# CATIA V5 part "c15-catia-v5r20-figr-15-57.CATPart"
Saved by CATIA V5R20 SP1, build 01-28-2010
Part number: Part1
Bounding box of the stored display mesh (mm): x -92.936 to 49.742, y -31.904 to 31.904, z 0 to 63.808
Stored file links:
  D:\v5_r20\psrt_files_downloaded\c15\c15-catia-v5r20-figr-15-57.CATPart
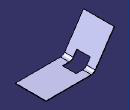
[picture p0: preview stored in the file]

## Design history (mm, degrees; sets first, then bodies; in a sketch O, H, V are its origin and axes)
SheetMetalParameters1: Thickness 1, BendRadius 10, KFactor 0.5 {= log(min(100,max(20*SheetMetalParameters1.BendRadius,SheetMetalParameters1.Thickness)/SheetMetalParameters1.Thickness))/log(100)/2}, ReliefRadialLength 1, ReliefAxialLength 2, MinimumBendRadius 0
Body1 (main body)
  Sketch1 on xy-plane, origin (0, 0, 0), H (1, 0, 0), V (0, 1, 0)
    line L1 (49.7419, 31.9042) -> (49.7419, -31.9042)
    line L2 (49.7419, -31.9042) -> (-49.7419, -31.9042)
    line L3 (-49.7419, -31.9042) -> (-49.7419, 31.9042)
    line L4 (-49.7419, 31.9042) -> (49.7419, 31.9042)
    vertical: L1 V, L3 V
    horizontal: L2 H, L4 H
    equidistance: L1 L3 O, L2 L4 O
  Wall1: Thickness 1, Profile Sketch1
  d_NewWallOnEdge1: NewWallOnEdge_Edge edge [face of Wall1 | face of Wall1], NewWallOnEdge_Length 63.8083, NewWallOnEdge_HeightLimitOffset 0, NewWallOnEdge_WidthOffset1 0, NewWallOnEdge_WidthOffset2 0, NewWallOnEdge_Angle 124, NewWallOnEdge_BendRadiusValue 10 {= SheetMetalParameters1.BendRadius}, NewWallOnEdge_BendTable SheetMetalParameters1, KFacteur 0.5 {= log(min(100,max(20*d_NewWallOnEdge1.Radius,SheetMetalParameters1.Thickness)/SheetMetalParameters1.Thickness))/log(100)/2}
  Sketch2 on face of d_NewWallOnEdge1, origin (0, 0, 1), H (1, 0, 0), V (0, 1, 0)
    point P1 (-49.1841, 0)
    line L1 (-30.5497, 14.1437) -> (-30.5497, -14.1437)
    line L2 (-30.5497, -14.1437) -> (-67.8185, -14.1437)
    line L3 (-67.8185, -14.1437) -> (-67.8185, 14.1437)
    line L4 (-67.8185, 14.1437) -> (-30.5497, 14.1437)
    coincidence: P1 H
    vertical: L1 V, L3 V
    horizontal: L2 H, L4 H
    equidistance: L1 L3 P1, L2 L4 P1
  CutOut1: Direction Sketch2, EndLimit through (limit type 2), Orientation true, Profile Sketch2, StartLimit through (limit type 2)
